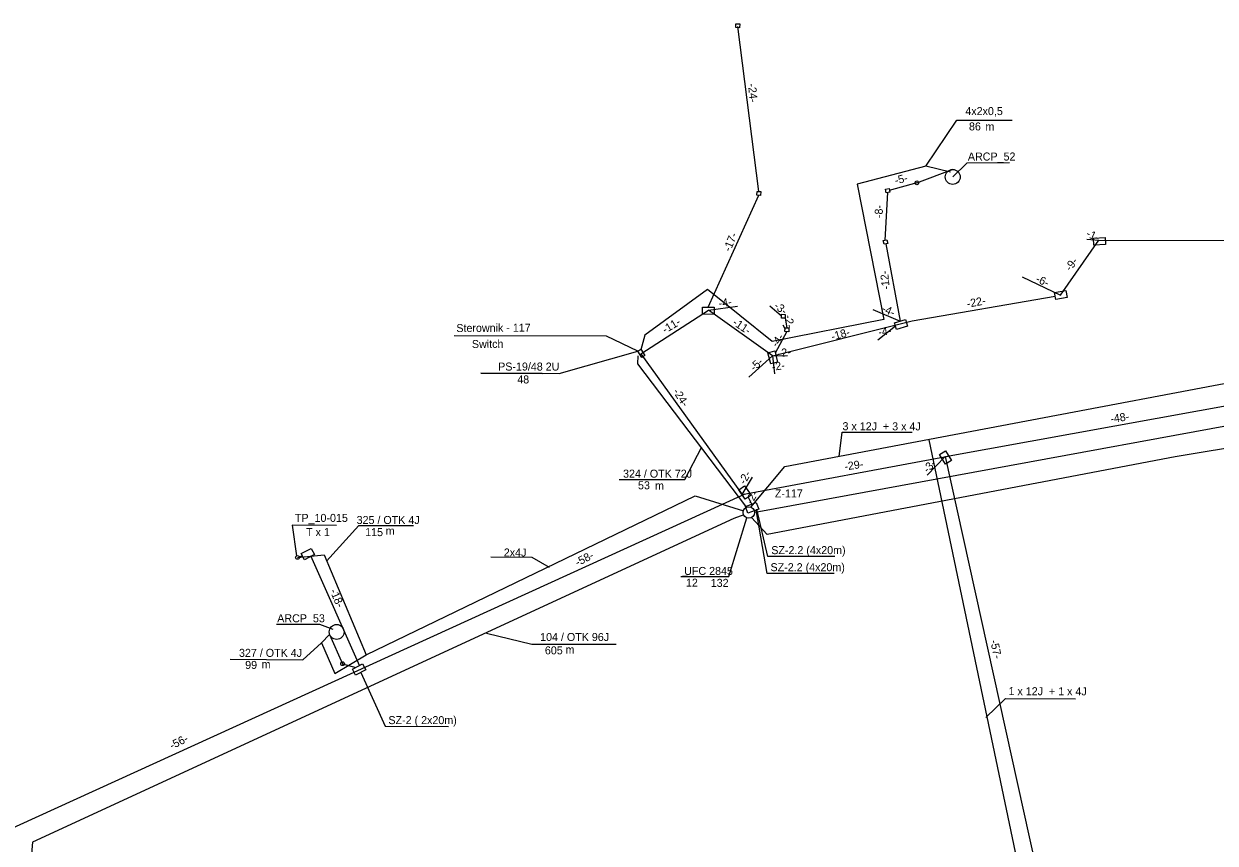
# Model space of a CAD drawing. Extents: x 6494530 to 6506885, y 5884901 to 5892312.
# Drawn here: x 6500365.8 to 6500525.8, y 5886893.9 to 5887003.9 of the extents above; entities that cross this region are included whole.
import ezdxf

# ---------------------------------------------------------------- set-up
doc = ezdxf.new("R2010")
doc.units = 0
for name, color, linetype in [('kabel do kamery ARCP', 7, 'Continuous'), ('kabel OTK do tab pasaż', 7, 'Continuous'), ('kabel W KANALIZACJI ISTN', 7, 'Continuous'), ('kamery ARCP_nowe', 7, 'Continuous'), ('Kanalizacja_proj', 7, 'Continuous'), ('NOWY OPIS STEROWNIKA', 7, 'Continuous'), ('NOWY OPIS ZŁĄCZA', 7, 'Continuous'), ('opis ARCP', 7, 'Continuous'), ('opis kabla CCTV_OTK', 7, 'Continuous'), ('opis kabla infopasażer_OTK', 7, 'Continuous'), ('opis kabla kamery ARCP', 7, 'Continuous'), ('opis kabla otk', 7, 'Continuous'), ('opis PS', 7, 'Continuous'), ('opis SZ-2', 7, 'Continuous'), ('opis SZ-2_2', 7, 'Continuous'), ('opis tablic inf przystankowej', 7, 'Continuous'), ('proj wysięgnik', 7, 'Continuous'), ('projektowany słup_do_kamery ARCP', 7, 'Continuous'), ('SKR-2', 7, 'Continuous'), ('sterownik', 7, 'Continuous'), ('Tekst2', 7, 'Continuous'), ('Warstwa 62', 7, 'Continuous'), ('WOJEWÓDZKIE', 7, 'Continuous')]:
    doc.layers.add(name, color=color, linetype=linetype)

msp = doc.modelspace()

# ---------------------------------------------------------------- linework, layer by layer
at = {"layer": 'kabel do kamery ARCP'}
msp.add_lwpolyline([(6500490.28, 5886984.03), (6500486.94, 5886984.83), (6500477.74, 5886982.4), (6500481.32, 5886964.23), (6500466.31, 5886961.29), (6500457.61, 5886968.28), (6500449.19, 5886962.12), (6500448.67, 5886960.17)], dxfattribs=at)
at = {"layer": 'kabel OTK do tab pasaż'}
for points in [[(6500463.43, 5886939.04), (6500468.03, 5886944.52), (6500562.82, 5886962.39), (6500664.85, 5886960.01), (6500663.71, 5886973.51)], [(6500487.34, 5886948.09), (6500498.95, 5886892.7), (6500479.81, 5886885.04), (6500461.64, 5886882.01), (6500463.76, 5886864.85), (6500467.31, 5886866.13)], [(6500402.56, 5886932.27), (6500406.12, 5886932.66), (6500411.79, 5886919.19), (6500455.97, 5886940.58), (6500462.47, 5886938.56)], [(6500406.86, 5886921.95), (6500405.77, 5886920.83), (6500407.56, 5886916.7), (6500411.79, 5886919.19)]]:
    msp.add_lwpolyline(points, dxfattribs=at)
at = {"layer": 'kabel W KANALIZACJI ISTN'}
for points in [[(6500448.26, 5886959.37), (6500448.2, 5886958.26), (6500462.85, 5886939)], [(6500464.01, 5886938.35), (6500562.12, 5886956.36), (6500668.41, 5886954.27), (6500745.05, 5886950.72), (6500747.14, 5886934.57)], [(6500563.33, 5886952.9), (6500520.44, 5886945.78), (6500465.62, 5886935.36), (6500463.52, 5886937.64)], [(6500462.5, 5886937.99), (6500461.18, 5886937.5), (6500366.93, 5886894.06), (6500365.54, 5886876.94), (6500309.61, 5886878.56), (6500172.98, 5886882.25), (6500149.6, 5886882.33), (6500092.15, 5886883.59), (6500064.17, 5886878.79), (6500044.52, 5886871.14), (6500004.6, 5886853.38), (6500010.59, 5886841.85), (6500004.26, 5886839.17), (6500001.73, 5886830.88), (6499991.08, 5886822.6), (6499990.45, 5886820.26), (6499985.2, 5886819)]]:
    msp.add_lwpolyline(points, dxfattribs=at)
msp.add_circle((6500463.18, 5886938.32), 0.757, dxfattribs=at)
at = {"layer": 'kamery ARCP_nowe'}
for centre in [(6500490.57, 5886983.38), (6500407.81, 5886922.29)]:
    msp.add_circle(centre, 1, dxfattribs=at)
at = {"layer": 'Kanalizacja_proj'}
for p, q in [((6500505.06, 5886967.5), (6500510.18, 5886974.87)), ((6500508.58, 5886975.02), (6500510.18, 5886974.87)), ((6500510.18, 5886974.87), (6500562.2, 5886974.78)), ((6500499.88, 5886969.97), (6500505.06, 5886967.5)), ((6500485.13, 5886964.04), (6500504.33, 5886967.36)), ((6500448.66, 5886959.62), (6500457.75, 5886965.5)), ((6500457.75, 5886965.5), (6500461.64, 5886966.01)), ((6500466.35, 5886959.35), (6500457.75, 5886965.5)), ((6500466.35, 5886959.35), (6500485.13, 5886964.04)), ((6500448.66, 5886959.62), (6500462.28, 5886940.74)), ((6500466.35, 5886959.35), (6500463.17, 5886956.48)), ((6500466.35, 5886959.35), (6500468.35, 5886959.38)), ((6500466.35, 5886959.35), (6500466.63, 5886956.96)), ((6500489.58, 5886945.84), (6500535.32, 5886954.11)), ((6500462.28, 5886940.74), (6500490.18, 5886945.94)), ((6500489.57, 5886945.82), (6500487.13, 5886943.33)), ((6500489.57, 5886945.82), (6500501.7, 5886890.91)), ((6500462.28, 5886940.74), (6500463.69, 5886943.08)), ((6500360.54, 5886894.29), (6500462.68, 5886940.81))]:
    msp.add_line(p, q, dxfattribs=at)
for points in [[(6500461.92, 5887003.41), (6500461.42, 5887003.43), (6500461.45, 5887003.93), (6500461.95, 5887003.91)], [(6500464.76, 5886980.9), (6500464.26, 5886980.93), (6500464.29, 5886981.43), (6500464.79, 5886981.4)], [(6500482.11, 5886981.35), (6500481.61, 5886981.26), (6500481.52, 5886981.75), (6500482.01, 5886981.84)], [(6500481.83, 5886974.44), (6500481.34, 5886974.34), (6500481.24, 5886974.84), (6500481.73, 5886974.93)], [(6500468.05, 5886964.41), (6500467.55, 5886964.43), (6500467.57, 5886964.93), (6500468.07, 5886964.91)], [(6500468.53, 5886962.6), (6500468.03, 5886962.62), (6500468.06, 5886963.12), (6500468.56, 5886963.1)]]:
    msp.add_lwpolyline(points, close=True, dxfattribs=at)
at = {"layer": 'NOWY OPIS STEROWNIKA'}
msp.add_lwpolyline([(6500448.26, 5886959.99), (6500444.04, 5886962.01), (6500423.59, 5886962.05)], dxfattribs=at)
at = {"layer": 'opis ARCP'}
for points in [[(6500498.21, 5886985.25), (6500492.47, 5886985.22), (6500490.57, 5886983.38)], [(6500407.36, 5886922.62), (6500405.56, 5886923.28), (6500399.73, 5886923.28)]]:
    msp.add_lwpolyline(points, dxfattribs=at)
at = {"layer": 'opis kabla infopasażer_OTK'}
for points in [[(6500406.46, 5886931.78), (6500410.78, 5886936.56), (6500418.12, 5886936.56)], [(6500393.5, 5886918.61), (6500403.26, 5886918.55), (6500405.77, 5886920.83)]]:
    msp.add_lwpolyline(points, dxfattribs=at)
at = {"layer": 'opis kabla kamery ARCP'}
msp.add_lwpolyline([(6500486.94, 5886984.83), (6500491.14, 5886990.99), (6500498.55, 5886990.99)], dxfattribs=at)
at = {"layer": 'opis kabla otk'}
for points in [[(6500475.33, 5886945.82), (6500475.73, 5886949.12), (6500485.12, 5886949.1)], [(6500445.74, 5886942.77), (6500454.56, 5886942.75), (6500456.86, 5886947.13)], [(6500428.53, 5886932.36), (6500434.01, 5886932.33), (6500436.34, 5886930.98)], [(6500427.95, 5886922.1), (6500434.01, 5886920.65), (6500445.36, 5886920.63)], [(6500495, 5886910.8), (6500497.64, 5886913.34), (6500507.04, 5886913.32)]]:
    msp.add_lwpolyline(points, dxfattribs=at)
at = {"layer": 'opis PS'}
for points in [[(6500433.86, 5886956.97), (6500427.18, 5886957.01), (6500435.42, 5886956.98), (6500427.18, 5886957.01), (6500437.68, 5886956.97), (6500448.26, 5886959.99)], [(6500454.04, 5886929.73), (6500454.08, 5886929.71), (6500454.92, 5886929.71), (6500454.27, 5886929.71), (6500460.49, 5886929.73), (6500462.93, 5886937.6)]]:
    msp.add_lwpolyline(points, dxfattribs=at)
at = {"layer": 'opis SZ-2'}
msp.add_lwpolyline([(6500411.05, 5886916.82), (6500414.33, 5886909.63), (6500422.84, 5886909.61)], dxfattribs=at)
at = {"layer": 'opis SZ-2_2'}
for points in [[(6500474.65, 5886930.11), (6500465.62, 5886930.11), (6500464.16, 5886938.7)], [(6500474.75, 5886932.4), (6500465.72, 5886932.4), (6500464.27, 5886938.79)]]:
    msp.add_lwpolyline(points, dxfattribs=at)
at = {"layer": 'opis tablic inf przystankowej'}
msp.add_lwpolyline([(6500407.77, 5886936.59), (6500401.83, 5886936.64), (6500402.4, 5886932.49)], dxfattribs=at)
at = {"layer": 'proj wysięgnik'}
for p, q in [((6500485.76, 5886982.58), (6500490.62, 5886984.42)), ((6500406.86, 5886921.95), (6500408.6, 5886918.02))]:
    msp.add_line(p, q, dxfattribs=at)
at = {"layer": 'projektowany słup_do_kamery ARCP'}
for centre in [(6500485.76, 5886982.58), (6500408.6, 5886918.02)]:
    msp.add_circle(centre, 0.25, dxfattribs=at)
at = {"layer": 'SKR-2'}
for points in [[(6500509.53, 5886974.22), (6500509.49, 5886975.17), (6500511.03, 5886975.25), (6500511.07, 5886974.3)], [(6500504.43, 5886966.92), (6500504.26, 5886967.86), (6500505.78, 5886968.13), (6500505.95, 5886967.2)], [(6500456.97, 5886964.92), (6500456.96, 5886965.87), (6500458.5, 5886965.88), (6500458.51, 5886964.93)], [(6500483.03, 5886962.87), (6500482.75, 5886963.78), (6500484.23, 5886964.23), (6500484.51, 5886963.32)], [(6500467.05, 5886958.51), (6500466.12, 5886958.28), (6500465.75, 5886959.78), (6500466.68, 5886960.01)], [(6500490.42, 5886945.3), (6500489.61, 5886944.8), (6500488.8, 5886946.11), (6500489.61, 5886946.61)], [(6500463.47, 5886940.63), (6500462.68, 5886940.1), (6500461.82, 5886941.38), (6500462.61, 5886941.91)], [(6500464.18, 5886939.66), (6500464.5, 5886938.76), (6500463.05, 5886938.24), (6500462.73, 5886939.14)], [(6500404.4, 5886933.51), (6500404.84, 5886932.67), (6500403.47, 5886931.96), (6500403.03, 5886932.8)], [(6500411.29, 5886918.02), (6500411.73, 5886917.18), (6500410.36, 5886916.46), (6500409.92, 5886917.31)]]:
    msp.add_lwpolyline(points, close=True, dxfattribs=at)
at = {"layer": 'sterownik'}
msp.add_lwpolyline([(6500448.26, 5886959.99), (6500448.67, 5886960.24), (6500449.21, 5886959.38), (6500448.79, 5886959.13)], close=True, dxfattribs=at)
at = {"layer": 'Tekst2'}
for p, q in [((6500464.54, 5886981.42), (6500461.71, 5887003.57)), ((6500481.49, 5886974.88), (6500481.86, 5886981.3)), ((6500482.06, 5886981.6), (6500485.8, 5886982.62)), ((6500457.73, 5886965.87), (6500464.51, 5886980.92)), ((6500481.58, 5886974.39), (6500483.49, 5886964.01)), ((6500467.56, 5886964.68), (6500466.01, 5886966.02)), ((6500479.82, 5886965.59), (6500483.49, 5886964.01)), ((6500467.74, 5886963.53), (6500468.07, 5886962.92)), ((6500468.05, 5886964.41), (6500468.27, 5886963.1)), ((6500468.28, 5886962.61), (6500466.72, 5886959.71)), ((6500482.89, 5886963.33), (6500480.52, 5886961.45)), ((6500463.1, 5886940.39), (6500463.56, 5886939.39)), ((6500402.74, 5886932.42), (6500403.28, 5886932.51)), ((6500404.31, 5886932.55), (6500410.86, 5886917.75)), ((6500408.6, 5886918.02), (6500410.39, 5886917.5))]:
    msp.add_line(p, q, dxfattribs=at)
at = {"layer": 'Warstwa 62'}
msp.add_circle((6500402.54, 5886932.29), 0.25, dxfattribs=at)

# ---------------------------------------------------------------- texts
at = {"layer": 'NOWY OPIS STEROWNIKA'}
for s, p in [('Sterownik - 117', (6500423.89, 5886962.55)), ('Switch ', (6500425.98, 5886960.4))]:
    msp.add_text(s, height=1.075, rotation=0.3174, dxfattribs=at).set_placement(p)
at = {"layer": 'NOWY OPIS ZŁĄCZA'}
msp.add_text('Z-117', height=1.075, dxfattribs=at).set_placement((6500466.67, 5886940.34))
at = {"layer": 'opis ARCP'}
for s, p in [('ARCP_52', (6500492.6, 5886985.58)), ('ARCP_53', (6500399.83, 5886923.58))]:
    msp.add_text(s, height=1.075, dxfattribs=at).set_placement(p)
at = {"layer": 'opis kabla CCTV_OTK'}
for s, height, p in [('324 / OTK 72J', 1.075, (6500446.28, 5886943)), ('53', 1.075, (6500448.29, 5886941.44)), ('m', 1.07, (6500450.58, 5886941.4)), ('104 / OTK 96J', 1.075, (6500435.14, 5886921.07)), ('605', 1.075, (6500435.78, 5886919.28)), ('m', 1.07, (6500438.56, 5886919.38))]:
    msp.add_text(s, height=height, dxfattribs=at).set_placement(p)
at = {"layer": 'opis kabla infopasażer_OTK'}
for s, height, p in [('325 / OTK 4J', 1.075, (6500410.49, 5886936.78)), ('115', 1.075, (6500411.64, 5886935.15)), ('m', 1.07, (6500414.4, 5886935.33)), ('327 / OTK 4J', 1.075, (6500394.69, 5886918.94)), ('99', 1.075, (6500395.52, 5886917.32)), ('m', 1.07, (6500397.73, 5886917.41))]:
    msp.add_text(s, height=height, dxfattribs=at).set_placement(p)
at = {"layer": 'opis kabla kamery ARCP'}
for s, height, p in [('4x2x0,5', 1.075, (6500492.26, 5886991.68)), ('86', 1.075, (6500492.75, 5886989.62)), ('m', 1.07, (6500494.96, 5886989.6))]:
    msp.add_text(s, height=height, dxfattribs=at).set_placement(p)
at = {"layer": 'opis kabla otk'}
for s, p in [('3 x 12J  + 3 x 4J', (6500475.76, 5886949.37)), ('2x4J', (6500430.26, 5886932.42)), ('1 x 12J  + 1 x 4J', (6500498.06, 5886913.8))]:
    msp.add_text(s, height=1.075, rotation=359.8395, dxfattribs=at).set_placement(p)
at = {"layer": 'opis PS'}
for s, p in [('PS-19/48 2U', (6500429.5, 5886957.38)), ('48', (6500432.07, 5886955.65)), ('UFC 2845', (6500454.49, 5886929.94)), ('12', (6500454.73, 5886928.36)), ('132', (6500458.06, 5886928.34))]:
    msp.add_text(s, height=1.075, dxfattribs=at).set_placement(p)
at = {"layer": 'opis SZ-2'}
msp.add_text('SZ-2 ( 2x20m)', height=1.075, dxfattribs=at).set_placement((6500414.76, 5886909.91))
at = {"layer": 'opis SZ-2_2'}
for p in [(6500466.19, 5886932.73), (6500466.09, 5886930.44)]:
    msp.add_text('SZ-2.2 (4x20m)', height=1.075, dxfattribs=at).set_placement(p)
at = {"layer": 'opis tablic inf przystankowej'}
for s, p in [('TP_10-015', (6500402.2, 5886937.06)), ('T x 1', (6500403.7, 5886935.16))]:
    msp.add_text(s, height=1.075, dxfattribs=at).set_placement(p)
at = {"layer": 'WOJEWÓDZKIE'}
for s, rotation, p in [('-24-', 275.1648, (6500463.07, 5886995.87)), ('-5-', 13.8435, (6500482.9, 5886982.36)), ('-8-', 89.1355, (6500481.16, 5886977.84)), ('-17-', 67.4492, (6500460.69, 5886973.27)), ('-1-', 335.4606, (6500508.39, 5886975.42)), ('-9-', 52.9402, (6500506.39, 5886970.65)), ('-12-', 95.2955, (6500482.11, 5886968.29)), ('-6-', 335.4606, (6500501.62, 5886969.32)), ('-4-', 8.1508, (6500459.19, 5886965.86)), ('-22-', 10.6755, (6500492.56, 5886965.81)), ('-3-', 322.772, (6500466.45, 5886965.86)), ('-4-', 335.4606, (6500480.93, 5886965.33)), ('-11-', 30.7167, (6500451.93, 5886962.32)), ('-11-', 326.0968, (6500460.89, 5886963.6)), ('-2-', 279.2153, (6500467.96, 5886964.76)), ('-4-', 55.627, (6500466.97, 5886960.43)), ('-18-', 15.6088, (6500474.39, 5886961.4)), ('-4-', 8.1508, (6500480.64, 5886962)), ('-2-', 8.1508, (6500467.16, 5886959.15)), ('-5-', 42.6469, (6500463.91, 5886957.23)), ('-2-', 8.1508, (6500466.34, 5886957.34)), ('-24-', 302.8965, (6500452.93, 5886954.56)), ('-48-', 8.3488, (6500511.81, 5886950.35)), ('-29-', 8.3488, (6500476.09, 5886943.96)), ('-3-', 45.6363, (6500487.2, 5886943.56)), ('-2-', 61.489, (6500462.68, 5886942.01)), ('-2-', 61.489, (6500463.63, 5886939.36)), ('-58-', 26.6674, (6500440.17, 5886931.08)), ('-18-', 293.3808, (6500406.87, 5886927.8)), ('-57-', 282.0403, (6500495.6, 5886921.1)), ('-56-', 26.6674, (6500385.69, 5886906.49))]:
    msp.add_text(s, height=1.075, rotation=rotation, dxfattribs=at).set_placement(p)

doc.saveas('drawing.dxf')
